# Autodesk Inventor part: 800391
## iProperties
Created: 2007-10
Part Number: 800391
Document SubType Name: Modeling
Designer: TC
Density: 7.85 g/cm^3
Mass: 5.27713 g
Surface Area: 7.0923 cm^2
Volume: 0.672246 cm^3
Material: Steel
Description: SHIM 8.7 MM X 3 MM
Component Category: Fasteners
Author: TC
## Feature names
1. Revolution1
